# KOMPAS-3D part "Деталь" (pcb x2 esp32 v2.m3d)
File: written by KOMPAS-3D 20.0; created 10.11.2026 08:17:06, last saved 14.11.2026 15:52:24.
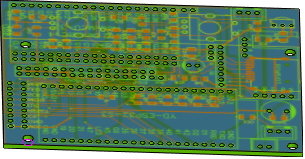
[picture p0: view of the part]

Document properties: Полное имя файла: D:\myProjects\Progect_esp32\box_compas\esp32\pcb x2 esp32 v2.m3d

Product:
- Part/product: Деталь
    Масса: 0.0646786

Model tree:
1. Эскиз:1
2. Элемент выдавливания:1
     Расстояние 1 = 1.5
3. Эскиз:3  (with: Элемент выдавливания:1)
4. Элемент выдавливания:5
     Расстояние 2 = 1.5
5. Массив по сетке:3  (with: Элемент выдавливания:5, Эскиз:3)  (4 pattern instances)
     Шаг 1 = 76.08; Угол раствора = -90; Шаг 2 = 44.2
6. Эскиз:7  (with: Элемент выдавливания:1)
7. Элемент выдавливания:6
     Расстояние 2 = 1.5
8. Массив по сетке:4  (with: Элемент выдавливания:6, Эскиз:7)  (44 pattern instances)
     Шаг 1 = 2.54; Угол раствора = -90; Шаг 2 = 25.4
9. Эскиз:8  (with: Элемент выдавливания:1)
10. Элемент выдавливания:7
     Расстояние 2 = 1.5
11. Массив по сетке:5  (with: Элемент выдавливания:7, Эскиз:8)  (38 pattern instances)
     Шаг 1 = 2.54; Угол раствора = 90; Шаг 2 = 25.4
12. Эскиз:10  (with: Элемент выдавливания:1)
13. Элемент выдавливания:9
     Расстояние 2 = 1.5
14. Массив по сетке:7  (with: Элемент выдавливания:9, Эскиз:10, Элемент выдавливания:1)  (2 pattern instances)
     Шаг 1 = 2.54; Угол раствора = -90; Шаг 2 = 2.54
15. Эскиз:11  (with: Элемент выдавливания:1)
16. Элемент выдавливания:10
     Расстояние 2 = 1.5
17. Массив по сетке:8  (with: Элемент выдавливания:10, Эскиз:11)  (3 pattern instances)
     Шаг 1 = 2.54; Угол раствора = 90
18. Эскиз:12  (with: Элемент выдавливания:1)
19. Элемент выдавливания:11
     Расстояние 2 = 1.5
20. Массив по сетке:9  (with: Элемент выдавливания:11, Эскиз:12)  (5 pattern instances)
     Шаг 1 = 2.54; Угол раствора = 90
21. Эскиз:13  (with: Элемент выдавливания:1)
22. Элемент выдавливания:12
     Расстояние 2 = 1.5
23. Массив по сетке:10  (with: Элемент выдавливания:12, Эскиз:13)  (19 pattern instances)
     Шаг 1 = 2.54; Угол раствора = 90
24. Эскиз:14  (with: Элемент выдавливания:1)
25. Элемент выдавливания:13
     Расстояние 2 = 1.5
26. Массив по сетке:11  (with: Элемент выдавливания:13, Эскиз:14)  (8 pattern instances)
     Шаг 1 = 10; Угол раствора = -90; Шаг 2 = 2.54
27. Эскиз:15  (with: Элемент выдавливания:1)
28. Элемент выдавливания:14
     Расстояние 2 = 1.5
29. Массив по сетке:12  (with: Элемент выдавливания:14, Эскиз:15)  (3 pattern instances)
     Шаг 1 = 10; Угол раствора = -90; Шаг 2 = 2.54
30. Эскиз:16  (with: Элемент выдавливания:1)
31. Элемент выдавливания:15
     Расстояние 2 = 1.5
32. Массив по сетке:13  (with: Элемент выдавливания:15, Эскиз:16)  (4 pattern instances)
     Шаг 1 = 10; Угол раствора = -90; Шаг 2 = 2.54
33. Эскиз:17  (with: Элемент выдавливания:1, Элемент выдавливания:5)
34. Элемент выдавливания:16
     Расстояние 2 = 1.5
35. Массив по сетке:14  (with: Элемент выдавливания:16, Эскиз:17)  (9 pattern instances)
     Шаг 1 = 10; Угол раствора = 90; Шаг 2 = 2.54; Геометрический массив = 128
36. Эскиз:18  (with: Элемент выдавливания:1, Элемент выдавливания:5)
37. Элемент выдавливания:17
     Расстояние 2 = 1.5
38. Массив по сетке:15  (with: Элемент выдавливания:17, Эскиз:18)  (9 pattern instances)
     Шаг 1 = 10; Угол раствора = 90; Шаг 2 = 2.54; Геометрический массив = 128
39. Эскиз:19  (with: Элемент выдавливания:1)
40. Элемент выдавливания:18
     Расстояние 2 = 1.5
41. Массив по сетке:16  (with: Элемент выдавливания:18, Эскиз:19)  (3 pattern instances)
     Шаг 1 = 2.54; Угол раствора = 90; Геометрический массив = 128
42. Эскиз:20  (with: Элемент выдавливания:1)
43. Элемент выдавливания:19
     Расстояние 2 = 1.5
44. Массив по сетке:17  (with: Элемент выдавливания:19, Эскиз:20)  (17 pattern instances)
     Шаг 1 = 2.54; Угол раствора = 90; Геометрический массив = 128
45. Эскиз:21  (with: Элемент выдавливания:1, Элемент выдавливания:19)
46. Элемент выдавливания:20
     Расстояние 2 = 1.5
47. Массив по сетке:18  (with: Элемент выдавливания:20, Эскиз:21)  (16 pattern instances)
     Шаг 1 = 2.54; Угол раствора = 90; Геометрический массив = 128
48. Эскиз:22  (with: Элемент выдавливания:1)
49. Элемент выдавливания:21
     Расстояние 2 = 1.5
50. Массив по сетке:19  (with: Элемент выдавливания:21, Эскиз:22)  (2 pattern instances)
     Шаг 1 = 2.54; Угол раствора = 90; Геометрический массив = 128
51. Эскиз:23  (with: Элемент выдавливания:1)
52. Элемент выдавливания:22
     Расстояние 2 = 1.5
53. Массив по сетке:20  (with: Элемент выдавливания:22, Эскиз:23)  (3 pattern instances)
     Шаг 1 = 2.54; Угол раствора = 90; Геометрический массив = 128
54. Эскиз:24  (with: Элемент выдавливания:1)
55. Элемент выдавливания:23
     Расстояние 2 = 1.5
56. Массив по сетке:21  (with: Элемент выдавливания:23, Эскиз:24)  (2 pattern instances)
     Шаг 1 = 2.5; Угол раствора = 90; Геометрический массив = 128
57. Эскиз:25  (with: Элемент выдавливания:1)
58. Элемент выдавливания:24
     Расстояние 2 = 1.5
59. Массив по сетке:22  (with: Элемент выдавливания:24, Эскиз:25)  (2 pattern instances)
     Шаг 1 = 5; Угол раствора = 90; Геометрический массив = 128

Referenced files in D:\myProjects\Progect_esp32\box_compas\esp32\pcb v2\: pcb ESP32 dual up.png
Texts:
  pcb v2\pcb ESP32 dual up.png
